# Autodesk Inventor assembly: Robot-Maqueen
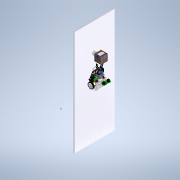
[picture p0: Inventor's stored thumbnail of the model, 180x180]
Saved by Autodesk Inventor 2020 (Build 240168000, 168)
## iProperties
Created: 2021-11
Part Number: Robot-Maqueen
Document SubType Name: Assembly
Designer: bruno
Author: bruno
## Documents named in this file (9)
- C:\Users\bruno\OneDrive\Bureau\Robot-Inventor\Robot-Maqueen\Robot-Maqueen.iam
- C:\Users\bruno\OneDrive\Bureau\Robot-Inventor\Robot-Maqueen\tapis.ipt
- C:\Users\bruno\OneDrive\Bureau\Robot-Inventor\Robot-Maqueen\Ensemble-base.iam
- C:\Users\bruno\OneDrive\Bureau\Robot-Inventor\Robot-Maqueen\Roulette.ipt
- C:\Users\bruno\OneDrive\Bureau\Robot-Inventor\Robot-Maqueen\roue.ipt
- C:\Users\bruno\OneDrive\Bureau\Robot-Inventor\Robot-Maqueen\Ensemble-pince.iam
- C:\Users\bruno\OneDrive\Bureau\Robot-Inventor\Robot-Maqueen\Ensemble-pince-2.iam
- C:\Users\bruno\OneDrive\Bureau\Robot-Inventor\Robot-Maqueen\support-colis.ipt
- C:\Users\bruno\OneDrive\Bureau\Robot-Inventor\Robot-Maqueen\colis.ipt
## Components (9 placed, 8 different names)
1. tapis:1 — Tangente:1, Tangente:2, Affleurement:1, Affleurement:2, Tangente:3, Placage:5
2. Ensemble-base:1 [sub-assembly] — Logement:2, Logement:3, Placage:1, Placage:2, Placage:3, Placage:4
3. Roulette:1 — Placage:1, Affleurement:2, Tangente:3
4. roue:1 — Logement:3, Tangente:2
5. roue:2 — Logement:2, Tangente:1, Affleurement:1
6. Ensemble-pince:1 [sub-assembly] — Placage:2, Affleurement:3, Rotation:1
7. Ensemble-pince-2:1 [sub-assembly] — Placage:3, Placage:4, Affleurement:3, Rotation:1
8. support-colis:1 — Placage:5, Placage:6
9. colis:1 — Placage:6
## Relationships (15: Mate 6, Tangent 3, Flush 3, Insert 2, RelateRotation 1)
- Logement:2 [Insert]: Ensemble-base:1 ↔ roue:2
- Logement:3 [Insert]: Ensemble-base:1 ↔ roue:1
- Tangente:1: tapis:1 ↔ roue:2
- Tangente:2: tapis:1 ↔ roue:1
- Affleurement:1 [Flush]: tapis:1 ↔ roue:2
- Placage:1 [Mate]: Ensemble-base:1 ↔ Roulette:1
- Affleurement:2 [Flush]: tapis:1 ↔ Roulette:1
- Tangente:3: tapis:1 ↔ Roulette:1
- Placage:2 [Mate]: Ensemble-base:1 ↔ Ensemble-pince:1
- Placage:3 [Mate]: Ensemble-base:1 ↔ Ensemble-pince-2:1
- Placage:4 [Mate]: Ensemble-base:1 ↔ Ensemble-pince-2:1
- Affleurement:3 [Flush]: Ensemble-pince:1 ↔ Ensemble-pince-2:1
- Rotation:1 [RelateRotation]: Ensemble-pince:1 ↔ Ensemble-pince-2:1
- Placage:5 [Mate]: tapis:1 ↔ support-colis:1
- Placage:6 [Mate]: support-colis:1 ↔ colis:1
